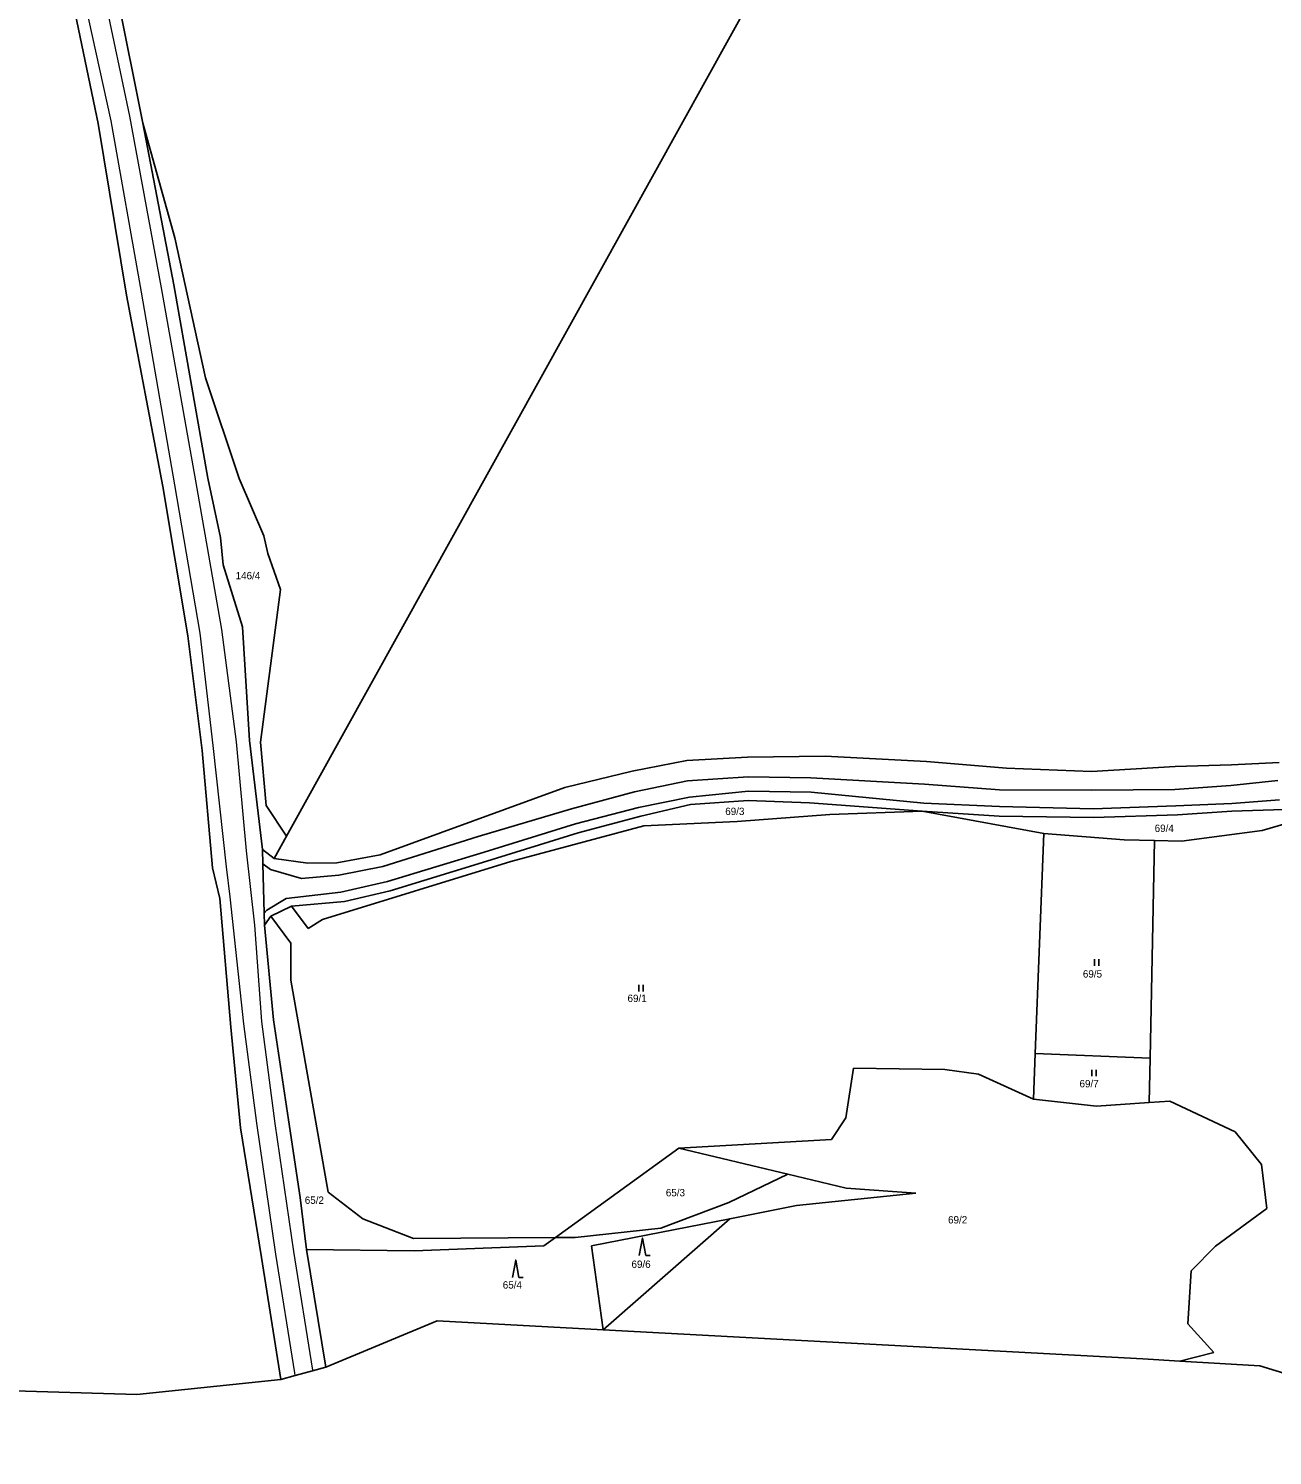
# Model space of a CAD drawing. Extents: x -885985 to -883535, y -1030025 to -1027941.
# Drawn here: x -885688.4 to -885401.2, y -1029014.3 to -1028684.8 of the extents above; entities that cross this region are included whole.
import ezdxf

# ---------------------------------------------------------------- set-up
doc = ezdxf.new("R2010")
doc.units = 0
doc.header["$LTSCALE"] = 0.68
for name, color, linetype, lineweight in [('1', 7, 'Continuous', 25), ('3', 7, 'Continuous', 25), ('4', 7, 'Continuous', 13)]:
    doc.layers.add(name, color=color, linetype=linetype, lineweight=lineweight)
doc.layers.add('2', color=7, linetype='Continuous')

msp = doc.modelspace()

# ---------------------------------------------------------------- linework, layer by layer
at = {"layer": '1'}
for p, q in [((-885537.71, -1028706.97), (-885446.58, -1028542.64)), ((-885662.04, -1028706.6), (-885668.08, -1028676.33)), ((-885678.06, -1028679.39), (-885672.35, -1028706.69)), ((-885672.35, -1028706.69), (-885665.8, -1028746.37)), ((-885654.66, -1028733.08), (-885662.04, -1028706.6)), ((-885654.87, -1028743.99), (-885662.04, -1028706.6)), ((-885628.83, -1028871.3), (-885537.71, -1028706.97)), ((-885647.53, -1028765.44), (-885654.66, -1028733.08)), ((-885665.8, -1028746.37), (-885657.4, -1028790.5)), ((-885647.02, -1028788.61), (-885654.87, -1028743.99)), ((-885639.76, -1028788.7), (-885647.53, -1028765.44)), ((-885644.12, -1028802.3), (-885647.02, -1028788.61)), ((-885634.1, -1028801.96), (-885639.76, -1028788.7)), ((-885657.4, -1028790.5), (-885651.65, -1028825.02)), ((-885643.49, -1028808.66), (-885644.12, -1028802.3)), ((-885633.13, -1028806.01), (-885634.1, -1028801.96)), ((-885630.21, -1028814.35), (-885633.13, -1028806.01)), ((-885639.02, -1028822.93), (-885643.49, -1028808.66)), ((-885634.89, -1028849.62), (-885630.21, -1028814.35)), ((-885651.65, -1028825.02), (-885648.35, -1028851.52)), ((-885637.37, -1028849.21), (-885639.02, -1028822.93)), ((-885648.35, -1028851.52), (-885645.94, -1028878.58)), ((-885634.42, -1028874.35), (-885637.37, -1028849.21)), ((-885633.54, -1028864.23), (-885634.89, -1028849.62)), ((-885536.42, -1028853.84), (-885549.05, -1028856.28)), ((-885522.39, -1028853.06), (-885536.42, -1028853.84)), ((-885504.49, -1028852.84), (-885522.39, -1028853.06)), ((-885481.05, -1028854.04), (-885504.49, -1028852.84)), ((-885462.61, -1028855.58), (-885481.05, -1028854.04)), ((-885442.95, -1028856.38), (-885462.61, -1028855.58)), ((-885423.61, -1028855.21), (-885442.95, -1028856.38)), ((-885410.62, -1028854.82), (-885423.61, -1028855.21)), ((-885399.64, -1028854.25), (-885410.62, -1028854.82)), ((-885549.05, -1028856.28), (-885564.55, -1028860.04)), ((-885536.26, -1028858.52), (-885548.47, -1028861.07)), ((-885522.23, -1028857.58), (-885536.26, -1028858.52)), ((-885507.76, -1028857.84), (-885522.23, -1028857.58)), ((-885481.51, -1028859.32), (-885507.76, -1028857.84)), ((-885399.89, -1028858.44), (-885410.76, -1028859.59)), ((-885564.55, -1028860.04), (-885607.23, -1028875.61)), ((-885548.47, -1028861.07), (-885563, -1028864.95)), ((-885535.81, -1028862.29), (-885522.16, -1028860.92)), ((-885522.16, -1028860.92), (-885507.71, -1028861.16)), ((-885507.71, -1028861.16), (-885481.66, -1028863.66)), ((-885464.22, -1028860.56), (-885481.51, -1028859.32)), ((-885442.92, -1028860.71), (-885464.22, -1028860.56)), ((-885423.69, -1028860.51), (-885442.92, -1028860.71)), ((-885410.76, -1028859.59), (-885423.69, -1028860.51)), ((-885628.83, -1028871.3), (-885633.54, -1028864.23)), ((-885563, -1028864.95), (-885584.62, -1028871.37)), ((-885562.14, -1028868.43), (-885547.56, -1028864.69)), ((-885547.56, -1028864.69), (-885535.81, -1028862.29)), ((-885535.57, -1028863.97), (-885547.06, -1028866.7)), ((-885522.23, -1028863.04), (-885535.57, -1028863.97)), ((-885508.05, -1028863.61), (-885522.23, -1028863.04)), ((-885482.05, -1028865.49), (-885508.05, -1028863.61)), ((-885503.39, -1028866.29), (-885482.05, -1028865.49)), ((-885464.3, -1028866.64), (-885482.05, -1028865.49)), ((-885482.05, -1028865.49), (-885453.97, -1028870.72)), ((-885481.66, -1028863.66), (-885464.21, -1028864.45)), ((-885464.21, -1028864.45), (-885442.54, -1028864.97)), ((-885442.54, -1028864.97), (-885423.52, -1028864.32)), ((-885423.52, -1028864.32), (-885410.55, -1028863.73)), ((-885410.58, -1028865.49), (-885423.13, -1028866.35)), ((-885398.51, -1028865.1), (-885410.58, -1028865.49)), ((-885410.55, -1028863.73), (-885399.54, -1028862.89)), ((-885583.17, -1028874.99), (-885562.14, -1028868.43)), ((-885547.06, -1028866.7), (-885561.46, -1028870.5)), ((-885546.37, -1028868.9), (-885524.79, -1028867.88)), ((-885524.79, -1028867.88), (-885503.39, -1028866.29)), ((-885442.41, -1028866.98), (-885464.3, -1028866.64)), ((-885423.13, -1028866.35), (-885442.41, -1028866.98)), ((-885403.56, -1028869.98), (-885390.91, -1028866.26)), ((-885631.68, -1028876.46), (-885628.83, -1028871.3)), ((-885584.62, -1028871.37), (-885606.6, -1028878.33)), ((-885561.46, -1028870.5), (-885582.58, -1028877.07)), ((-885577.04, -1028877.15), (-885546.37, -1028868.9)), ((-885455.94, -1028921.47), (-885453.97, -1028870.72)), ((-885453.97, -1028870.72), (-885435.39, -1028872.15)), ((-885422.16, -1028872.47), (-885403.56, -1028869.98)), ((-885634.33, -1028877.66), (-885634.42, -1028874.35)), ((-885634.42, -1028874.35), (-885631.68, -1028876.46)), ((-885605.55, -1028881.8), (-885583.17, -1028874.99)), ((-885435.39, -1028872.15), (-885428.39, -1028872.32)), ((-885428.39, -1028872.32), (-885429.43, -1028922.6)), ((-885428.39, -1028872.32), (-885422.16, -1028872.47)), ((-885645.94, -1028878.58), (-885644.25, -1028885.66)), ((-885634.33, -1028877.66), (-885634.02, -1028889.12)), ((-885632.54, -1028879.03), (-885634.33, -1028877.66)), ((-885623.96, -1028877.54), (-885631.68, -1028876.46)), ((-885617.24, -1028877.48), (-885623.96, -1028877.54)), ((-885620.57, -1028890.57), (-885577.04, -1028877.15)), ((-885607.23, -1028875.61), (-885617.24, -1028877.48)), ((-885606.6, -1028878.33), (-885616.76, -1028880.28)), ((-885582.58, -1028877.07), (-885604.88, -1028883.94)), ((-885625.39, -1028881.09), (-885632.54, -1028879.03)), ((-885616.76, -1028880.28), (-885625.39, -1028881.09)), ((-885616.27, -1028884.24), (-885605.55, -1028881.8)), ((-885628.91, -1028885.68), (-885616.27, -1028884.24)), ((-885604.88, -1028883.94), (-885615.46, -1028886.35)), ((-885644.25, -1028885.66), (-885641.73, -1028915.44)), ((-885634.02, -1028889.12), (-885633.4, -1028888.36)), ((-885633.4, -1028888.36), (-885628.91, -1028885.68)), ((-885632.49, -1028889.74), (-885627.7, -1028887.46)), ((-885615.46, -1028886.35), (-885627.7, -1028887.46)), ((-885627.7, -1028887.46), (-885623.88, -1028892.6)), ((-885633.95, -1028891.87), (-885634.02, -1028889.12)), ((-885633.95, -1028891.87), (-885632.49, -1028889.74)), ((-885627.87, -1028895.98), (-885632.49, -1028889.74)), ((-885623.88, -1028892.6), (-885620.57, -1028890.57)), ((-885631.85, -1028913.74), (-885633.95, -1028891.87)), ((-885627.87, -1028904.53), (-885627.87, -1028895.98)), ((-885619.26, -1028953.49), (-885627.87, -1028904.53)), ((-885628.39, -1028936.84), (-885631.85, -1028913.74)), ((-885641.73, -1028915.44), (-885639.49, -1028938.68)), ((-885456.35, -1028932.04), (-885455.94, -1028921.47)), ((-885455.94, -1028921.47), (-885429.43, -1028922.6)), ((-885429.43, -1028922.6), (-885429.64, -1028932.81)), ((-885497.9, -1028924.86), (-885499.67, -1028936.36)), ((-885476.81, -1028925.23), (-885497.9, -1028924.86)), ((-885469.05, -1028926.28), (-885476.81, -1028925.23)), ((-885456.35, -1028932.04), (-885469.05, -1028926.28)), ((-885441.81, -1028933.67), (-885456.35, -1028932.04)), ((-885429.64, -1028932.81), (-885441.81, -1028933.67)), ((-885424.87, -1028932.48), (-885429.64, -1028932.81)), ((-885409.77, -1028939.57), (-885424.87, -1028932.48)), ((-885625.7, -1028954.79), (-885628.39, -1028936.84)), ((-885499.67, -1028936.36), (-885503, -1028941.34)), ((-885639.49, -1028938.68), (-885634.65, -1028968.65)), ((-885403.67, -1028947.13), (-885409.77, -1028939.57)), ((-885538.27, -1028943.33), (-885566.76, -1028964.02)), ((-885503, -1028941.34), (-885538.27, -1028943.33)), ((-885513.05, -1028949.4), (-885538.27, -1028943.33)), ((-885402.45, -1028957.28), (-885403.67, -1028947.13)), ((-885526.67, -1028955.89), (-885513.05, -1028949.4)), ((-885499.62, -1028952.63), (-885513.05, -1028949.4)), ((-885611.23, -1028959.67), (-885619.26, -1028953.49)), ((-885511.08, -1028956.64), (-885483.55, -1028953.75)), ((-885483.55, -1028953.75), (-885499.62, -1028952.63)), ((-885624.23, -1028966.8), (-885625.7, -1028954.79)), ((-885542.37, -1028961.86), (-885526.67, -1028955.89)), ((-885526.46, -1028959.66), (-885511.08, -1028956.64)), ((-885414.32, -1028966), (-885402.45, -1028957.28)), ((-885599.53, -1028964.22), (-885611.23, -1028959.67)), ((-885558.45, -1028965.93), (-885526.46, -1028959.66)), ((-885555.71, -1028985.29), (-885526.46, -1028959.66)), ((-885566.76, -1028964.02), (-885599.53, -1028964.22)), ((-885566.76, -1028964.02), (-885569.39, -1028965.93)), ((-885566.76, -1028964.02), (-885562.16, -1028964)), ((-885562.16, -1028964), (-885542.37, -1028961.86)), ((-885599.38, -1028967.1), (-885624.23, -1028966.8)), ((-885619.78, -1028993.92), (-885624.23, -1028966.8)), ((-885569.39, -1028965.93), (-885599.38, -1028967.1)), ((-885555.71, -1028985.29), (-885558.45, -1028965.93)), ((-885419.91, -1028971.73), (-885414.32, -1028966)), ((-885634.65, -1028968.65), (-885630.13, -1028996.79)), ((-885420.73, -1028983.94), (-885419.91, -1028971.73)), ((-885594.09, -1028983.21), (-885619.78, -1028993.92)), ((-885555.71, -1028985.29), (-885594.09, -1028983.21)), ((-885414.68, -1028990.59), (-885420.73, -1028983.94)), ((-885431.09, -1028992.05), (-885555.71, -1028985.29)), ((-885422.54, -1028992.56), (-885414.68, -1028990.59)), ((-885619.78, -1028993.92), (-885622.85, -1028994.77)), ((-885422.54, -1028992.56), (-885431.09, -1028992.05)), ((-885404.12, -1028993.65), (-885422.54, -1028992.56)), ((-885335.51, -1029014.34), (-885404.12, -1028993.65)), ((-885630.13, -1028996.79), (-885663.44, -1029000.27)), ((-885626.84, -1028995.88), (-885630.13, -1028996.79)), ((-885622.85, -1028994.77), (-885626.84, -1028995.88)), ((-885663.44, -1029000.27), (-885694.26, -1028999.36))]:
    msp.add_line(p, q, dxfattribs=at)
at = {"layer": '3'}
for p, q in [((-885442.251, -1028901.21), (-885442.251, -1028899.71)), ((-885441.25, -1028901.21), (-885441.25, -1028899.71)), ((-885547.521, -1028907.15), (-885547.521, -1028905.65)), ((-885546.52, -1028907.15), (-885546.52, -1028905.65)), ((-885442.891, -1028926.77), (-885442.891, -1028925.27)), ((-885441.89, -1028926.77), (-885441.89, -1028925.27)), ((-885545.9, -1028968.12), (-885544.904, -1028968.12)), ((-885575.17, -1028973.21), (-885574.174, -1028973.21))]:
    msp.add_line(p, q, dxfattribs=at)
for points in [[(-885545.9, -1028968.12), (-885546.65, -1028964.12), (-885547.4, -1028968.12)], [(-885575.17, -1028973.21), (-885575.92, -1028969.21), (-885576.67, -1028973.21)]]:
    msp.add_lwpolyline(points, dxfattribs=at)
at = {"layer": '4'}
for p, q in [((-885670.93, -1028677.24), (-885665.08, -1028705.02)), ((-885669.32, -1028706.07), (-885675.45, -1028678.46)), ((-885662.36, -1028745.63), (-885669.32, -1028706.07)), ((-885665.08, -1028705.02), (-885657.77, -1028744.65)), ((-885654.65, -1028790.13), (-885662.36, -1028745.63)), ((-885657.77, -1028744.65), (-885649.9, -1028789.21)), ((-885649.9, -1028789.21), (-885643.86, -1028823.54)), ((-885648.79, -1028824.44), (-885654.65, -1028790.13)), ((-885645.8, -1028850.35), (-885648.79, -1028824.44)), ((-885643.86, -1028823.54), (-885640.48, -1028849.54)), ((-885642.71, -1028878.36), (-885645.8, -1028850.35)), ((-885640.48, -1028849.54), (-885638.2, -1028874.7)), ((-885638.2, -1028874.7), (-885636.26, -1028891.88)), ((-885641.88, -1028885.32), (-885642.71, -1028878.36)), ((-885638.73, -1028914.66), (-885641.88, -1028885.32)), ((-885636.26, -1028891.88), (-885634.63, -1028914.11)), ((-885635.71, -1028937.58), (-885638.73, -1028914.66)), ((-885634.63, -1028914.11), (-885631.58, -1028937.68)), ((-885631.29, -1028967.85), (-885635.71, -1028937.58)), ((-885631.58, -1028937.68), (-885627.2, -1028967.2)), ((-885627.2, -1028967.2), (-885622.84, -1028994.61)), ((-885626.91, -1028995.23), (-885631.29, -1028967.85)), ((-885626.84, -1028995.88), (-885626.91, -1028995.23)), ((-885622.84, -1028994.61), (-885622.85, -1028994.77))]:
    msp.add_line(p, q, dxfattribs=at)

# ---------------------------------------------------------------- texts
at = {"layer": '2'}
for s, p in [('146/4', (-885640.59, -1028811.965)), ('69/3', (-885527.53, -1028866.415)), ('69/4', (-885428.37, -1028870.325)), ('69/5', (-885444.95, -1028903.965)), ('69/1', (-885550.1, -1028909.595)), ('69/7', (-885445.72, -1028929.315)), ('65/2', (-885624.63, -1028956.225)), ('65/3', (-885541.25, -1028954.485)), ('69/2', (-885476.08, -1028960.755)), ('69/6', (-885549.18, -1028971.015)), ('65/4', (-885578.91, -1028975.795))]:
    msp.add_text(s, height=1.7, dxfattribs=at).set_placement(p)

doc.saveas('drawing.dxf')
